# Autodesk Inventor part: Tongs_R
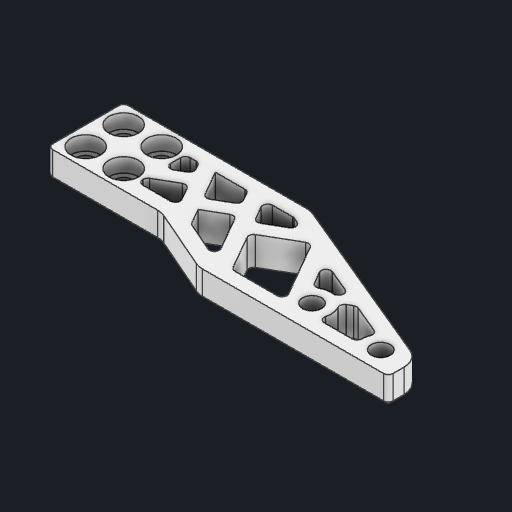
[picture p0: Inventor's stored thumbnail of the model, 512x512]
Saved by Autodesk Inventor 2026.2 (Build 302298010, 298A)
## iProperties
Created: 2026-05
Part Number: Tongs_R
Material: ABS 플라스틱
Document SubType Name: Modeling
Designer: work
Density: 1.06 g/cm^3
Appearance: 매끄러움 - 흰색
Author: work
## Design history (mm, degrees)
sketch "스케치1"
  geometry: L1 (-4, 4)-(4, 4); L2 (4, 4)-(4, -4); L3 (4, -4)-(-4, -4); L4 (-4, -4)-(-4, 4); L5 (-4, 4)-(4, -4); L6 (4, 4)-(-4, -4); L7 (-8, 8)-(8, 8); L8 (8, 8)-(8, -8); L9 (8, -8)-(-8, -8); L10 (-8, -8)-(-8, 8); L11 (-8, 8)-(8, -8); L12 (8, 8)-(-8, -8); L13 (-8, 8)-(-16, 8); L14 (-16, 8)-(-29.748, 14); L15 (-29.748, 14)-(-69.748, 14); L16 (-69.748, 14)-(-69.748, 8); L17 (-69.748, 8)-(-31.398, -8); L18 (-31.398, -8)-(-8, -8); L19 (-8, -5)-(-30.797, -5); L20 (-30.797, -5)-(-66.748, 9.999); L21 (-66.748, 9.999)-(-66.748, 11); L22 (-66.748, 11)-(-30.374, 11); L23 (-30.374, 11)-(-16.626, 5); L24 (-16.626, 5)-(-8, 5); L25 (-48.561, 11)-(-42.029, -0.314); L26 (-45.097, 11)-(-37.465, -2.218); L27 (-30.374, 11)-(-21.136, -5); L28 (-33.838, 11)-(-24.6, -5); L29 (-16.626, 5)-(-10.853, -5); L30 (-21.257, 7.021)-(-14.317, -5); L31 (-37.465, -2.218)-(-29.021, 2.657); L32 (-27.521, 0.059)-(-33.982, -3.671); L33 (-13.739, 0)-(-8, 3.314); L34 (-12.239, -2.598)-(-8, -0.15); L35 (-17.787, 1.011)-(-22.902, -1.942); L36 (-24.402, 0.656)-(-19.287, 3.609); L37 (-46.029, 6.614)-(-51.317, 3.561); L38 (-47.029, 8.346)-(-53.639, 4.53); C1 r 2 at (4, 4); C2 r 2 at (4, -4); C3 r 2 at (-4, -4); C4 r 2 at (-4, 4); 4 further points
  constraints: 76 end point, 24 point on line, 19 parallel, 8 midpoint, 6 perpendicular, 4 centre point, 4 coincident, 3 horizontal, 5 other
  dimensions: "d0" = 8 distance of L2.end L3.end; "d1" = 8 distance of L1.end L2.end; "d2" = 4 diameter of C1; "d3" = 4 diameter of C2; "d4" = 4 diameter of C3; "d5" = 4 diameter of C4; "d6" = 4 distance between parallel lines of L8 L2; "d7" = 8 distance of L7.start L13.end; "d8" = 15 distance of L13.end L14.end; "d9" = 40 distance of L14.end L15.end; "d10" = 6 distance of L15.end L16.end; "d11" = 38.34957 horizontal distance of L16.end L17.end; "d12" = 3 distance between parallel lines of L14 L23; "d13" = 3 distance between parallel lines of L25 L26; "d14" = 3 distance between parallel lines of L28 L27; "d15" = 3 distance between parallel lines of L30 L29; "d16" = 120 deg angle of L22 L28; "d17" = 3 distance between parallel lines of L35 L36; "d18" = 3 distance from line of L31 point (-30.752, -1.806); "d19" = 2 distance between parallel lines of L38 L37; "d20" = 8 distance from line of L25.end L37; "d21" = 3 distance between parallel lines of L34 L33
extrude "돌출1" new body sketch "스케치1" distance "d22" = 6; taper "d23" = 0 deg
sketch "스케치2"
  geometry: L1 (16, -8)-(29.748, -14) reference; L2 (29.748, -14)-(69.748, -14) reference; L3 (69.748, -14)-(69.748, -8) reference; L4 (69.748, -8)-(31.398, 8) reference; L5 (31.398, 8)-(-8, 8) reference; L6 (-8, 8)-(-8, -8) reference; L7 (-8, -8)-(16, -8) reference; L8 (27.521, -0.059)-(24.6, 5) reference; L9 (24.6, 5)-(30.797, 5) reference; L10 (30.797, 5)-(33.982, 3.671) reference; L11 (33.982, 3.671)-(27.521, -0.059) reference; L12 (12.239, 2.598)-(8, 0.15) reference; L13 (8, 0.15)-(8, 5) reference; L14 (8, 5)-(10.853, 5) reference; L15 (10.853, 5)-(12.239, 2.598) reference; L16 (17.787, -1.011)-(14.317, 5) reference; L17 (14.317, 5)-(21.136, 5) reference; L18 (21.136, 5)-(22.902, 1.942) reference; L19 (22.902, 1.942)-(17.787, -1.011) reference; L20 (46.029, -6.614)-(42.029, 0.314) reference; L21 (42.029, 0.314)-(51.317, -3.561) reference; L22 (51.317, -3.561)-(46.029, -6.614) reference; L23 (13.739, 0)-(16.626, -5) reference; L24 (16.626, -5)-(8, -5) reference; L25 (8, -5)-(8, -3.314) reference; L26 (8, -3.314)-(13.739, 0) reference; L27 (19.287, -3.609)-(24.402, -0.656) reference; L28 (24.402, -0.656)-(30.374, -11) reference; L29 (30.374, -11)-(21.257, -7.021) reference; L30 (21.257, -7.021)-(19.287, -3.609) reference; L31 (29.021, -2.657)-(37.465, 2.218) reference; L32 (37.465, 2.218)-(45.097, -11) reference; L33 (45.097, -11)-(33.838, -11) reference; L34 (33.838, -11)-(29.021, -2.657) reference; L35 (47.029, -8.346)-(53.639, -4.53) reference; L36 (53.639, -4.53)-(66.748, -9.999) reference; L37 (66.748, -9.999)-(66.748, -11) reference; L38 (66.748, -11)-(48.561, -11) reference; L39 (48.561, -11)-(47.029, -8.346) reference; C1 r 2 at (4, -4) reference; C2 r 2 at (4, 4) reference; C3 r 2 at (-4, 4) reference; C4 r 2 at (-4, -4) reference; 5 further points
  constraints: 4 coincident
hole "구멍1" sketch "스케치2" at (-4, -4), (4, -4), (4, 4), (-4, 4) diameter "d24" = 4; stored, may be unused: countersink angle "d28" = 90 deg, drill point angle "d30" = 118 deg; dims "d25" = 6, "d26" = 6.2, "d27" = 3, "d29" = 8
fillet "모깎기1" dims "d31" = 1
fillet "모깎기2" dims "d32" = 4
fillet "모깎기3" dims "d33" = 1
chamfer "모따기1" distance "d34" = 1; stored, may be unused: second distance "d35" = 2, angle "d36" = 45 deg
node "작업 평면1"
sketch "스케치3"
  geometry: L1 (69.748, -13)-(69.748, -10.665) reference; L2 (67.288, -6.974)-(32.137, 7.692) reference; L3 (30.597, 8)-(-7, 8) reference; L4 (-8, 7)-(-8, -7) reference; L5 (-7, -8)-(15.165, -8) reference; L6 (16.765, -8.334)-(28.983, -13.666) reference; L7 (30.583, -14)-(68.748, -14) reference; L8 (27.021, 0.807)-(25.466, 3.5) reference; L9 (26.332, 5)-(30.597, 5) reference; L10 (30.982, 4.923)-(32.117, 4.45) reference; L11 (32.232, 2.661)-(28.387, 0.441) reference; L12 (11.373, 2.098)-(9.5, 1.016) reference; L13 (8, 1.883)-(8, 4) reference; L14 (9, 5)-(10.275, 5) reference; L15 (11.141, 4.5)-(11.739, 3.464) reference; L16 (17.287, -0.145)-(14.317, 5) reference; L17 (14.317, 5)-(20.559, 5) reference; L18 (21.425, 4.5)-(22.402, 2.808) reference; L19 (22.036, 1.442)-(18.653, -0.511) reference; L20 (45.529, -5.748)-(43.508, -2.248) reference; L21 (44.759, -0.825)-(49.451, -2.783) reference; L22 (49.566, -4.572)-(46.895, -6.114) reference; L23 (14.239, -0.866)-(15.76, -3.5) reference; L24 (14.894, -5)-(9, -5) reference; L25 (8, -4)-(8, -3.891) reference; L26 (8.5, -3.025)-(12.873, -0.5) reference; L27 (19.287, -3.609)-(23.536, -1.156) reference; L28 (24.902, -1.522)-(28.854, -8.368) reference; L29 (27.588, -9.784)-(21.559, -7.153) reference; L30 (21.093, -6.736)-(19.287, -3.609) reference; L31 (29.887, -2.157)-(36.599, 1.718) reference; L32 (37.965, 1.352)-(44.231, -9.5) reference; L33 (43.365, -11)-(34.415, -11) reference; L34 (33.549, -10.5)-(29.521, -3.523) reference; L35 (47.895, -7.846)-(53.21, -4.777) reference; L36 (54.095, -4.72)-(64.538, -9.077) reference; L37 (64.153, -11)-(49.138, -11) reference; L38 (48.272, -10.5)-(47.529, -9.212) reference; C1 r 3.1 at (-4, 4) reference; C2 r 3.1 at (4, 4) reference; C3 r 3.1 at (4, -4) reference; C4 r 3.1 at (-4, -4) reference; C5 r 4 at (64.153, -10); C6 r 2 at (64.153, -10); C7 r 4 at (48.395, -8.712); C8 r 2 at (48.395, -8.712); A1 r 1 centre (68.748, -13) between (68.748, -14) and (69.748, -13) reference; A2 r 4 centre (65.748, -10.665) between (69.748, -10.665) and (67.288, -6.974) reference; A3 r 4 centre (30.597, 4) between (32.137, 7.692) and (30.597, 8) reference; A4 r 1 centre (-7, 7) between (-7, 8) and (-8, 7) reference; A5 r 1 centre (-7, -7) between (-8, -7) and (-7, -8) reference; A6 r 4 centre (15.165, -12) between (16.765, -8.334) and (15.165, -8) reference; A7 r 4 centre (30.583, -10) between (28.983, -13.666) and (30.583, -14) reference; A8 r 1 centre (26.332, 4) between (26.332, 5) and (25.466, 3.5) reference; A9 r 1 centre (30.597, 4) between (30.982, 4.923) and (30.597, 5) reference; A10 r 1 centre (31.732, 3.527) between (32.232, 2.661) and (32.117, 4.45) reference; A11 r 1 centre (27.887, 1.307) between (27.021, 0.807) and (28.387, 0.441) reference; A12 r 1 centre (9, 1.883) between (8, 1.883) and (9.5, 1.016) reference; A13 r 1 centre (9, 4) between (9, 5) and (8, 4) reference; A14 r 1 centre (10.275, 4) between (11.141, 4.5) and (10.275, 5) reference; A15 r 1 centre (10.873, 2.964) between (11.373, 2.098) and (11.739, 3.464) reference; A16 r 1 centre (20.559, 4) between (21.425, 4.5) and (20.559, 5) reference; A17 r 1 centre (21.536, 2.308) between (22.036, 1.442) and (22.402, 2.808) reference; A18 r 1 centre (18.153, 0.355) between (17.287, -0.145) and (18.653, -0.511) reference; A19 r 1 centre (44.374, -1.748) between (44.759, -0.825) and (43.508, -2.248) reference; A20 r 1 centre (49.066, -3.706) between (49.566, -4.572) and (49.451, -2.783) reference; A21 r 1 centre (46.395, -5.248) between (45.529, -5.748) and (46.895, -6.114) reference; A22 r 1 centre (14.894, -4) between (14.894, -5) and (15.76, -3.5) reference; A23 r 1 centre (9, -4) between (8, -4) and (9, -5) reference; A24 r 1 centre (9, -3.891) between (8.5, -3.025) and (8, -3.891) reference; A25 r 1 centre (13.373, -1.366) between (14.239, -0.866) and (12.873, -0.5) reference; A26 r 1 centre (24.036, -2.022) between (24.902, -1.522) and (23.536, -1.156) reference; A27 r 1 centre (27.988, -8.868) between (27.588, -9.784) and (28.854, -8.368) reference; A28 r 1 centre (21.959, -6.236) between (21.093, -6.736) and (21.559, -7.153) reference; A29 r 1 centre (37.099, 0.852) between (37.965, 1.352) and (36.599, 1.718) reference; A30 r 1 centre (43.365, -10) between (43.365, -11) and (44.231, -9.5) reference; A31 r 1 centre (34.415, -10) between (33.549, -10.5) and (34.415, -11) reference; A32 r 1 centre (30.387, -3.023) between (29.887, -2.157) and (29.521, -3.523) reference; A33 r 1 centre (53.71, -5.643) between (54.095, -4.72) and (53.21, -4.777) reference; A34 r 1 centre (64.153, -10) between (64.153, -11) and (64.538, -9.077) reference; A35 r 1 centre (49.138, -10) between (48.272, -10.5) and (49.138, -11) reference; A36 r 1 centre (48.395, -8.712) between (47.895, -7.846) and (47.529, -9.212) reference; A37 r 1 centre (48.395, -8.712) between (47.895, -7.846) and (47.529, -9.212) reference; 11 further points
  constraints: 4 centre point, 4 coincident
  dimensions: "d38" = 8 diameter of C5; "d41" = 4 diameter of C6; "d42" = 8 diameter of C7; "d43" = 4 diameter of C8
  node "투영된 루프2"
extrude "돌출2" join sketch "스케치3" stored distance "d44" = 10; taper "d45" = 0 deg
extrude "돌출3" cut sketch "스케치3" extent not by distance; stored distance "d46" = 0; taper "d47" = 0 deg
fillet "모깎기4" dims "d48" = 1
node "솔리드1"
node "투영된 루프1"
feature "A9D066F2-1C7D-4E18-AEED-F7BC21143FA4" dims "d24" = 4, "d25" = 6, "d26" = 6.2, "d27" = 3, "d28" = 90 deg, "d29" = 8, "d30" = 118 deg
other parameters: "d37" = 0
